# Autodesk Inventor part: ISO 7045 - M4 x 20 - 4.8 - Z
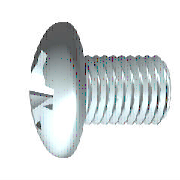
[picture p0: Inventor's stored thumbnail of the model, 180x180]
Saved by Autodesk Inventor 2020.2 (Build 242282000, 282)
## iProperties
Manager: www.cadconsulting.pl
Company: Fabian Stasiak CAD Consulting
Created: 2010-02
Part Number: ISO 7045 - M4 x 20 - 4.8 - Z
Material: Stal nierdzewna, 440C
Description: Śruba z łbem walcowym wypukłym z wgłębieniem krzyżowym
Document SubType Name: Modeling
Standard: ISO 7045
Designer: F.Stasiak
Standard Revision: 1994
Standards Organization: DIN
Language: pl-PL
Size Designation: M4 x 20 - 4.8 - Z
Categories: <MemberInstance><Categories><Category DisplayName="Mocowania" InternalName="e4da775c-781d-43d5-af7c-5136215cf5a6" Mnemonic="FSTN"><Category DisplayName="Śruby"
Density: 7.75 g/cm^3
Appearance: Metal-Stal
IsCustomPart: 0
Author: F.Stasiak
Subject: Zbiór ćwiczeń. Autodesk Inventor 2020. Kurs podstawowy
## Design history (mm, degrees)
body "Solid1"
sketch "Sketch1"
  geometry: L1 (20, 0)-(20, 2); L2 (20, 2)-(1.4, 2); L3 (3.962, 5.08)-(3.962, 5.08); L4 (-3.1, 0)-(-3.1, 3.892); L5 (-2.787, 1.994)-(-1.471, 1.338); L6 (-1.471, 1.338)-(-0.76, 0); L7 (-0.76, 0)-(20, 0); L8 (-8.108, 0)-(24.685, 0) reference; L9 (0, -1.016)-(0, 6.096) reference; L10 (-2.787, 1.994)-(-3.1, 2.15); L11 (-1.771, 3.938)-(-3.1, 3.892); L12 (-1.771, 3.938)-(0, 4); L13 (0, 4)-(0, 1.811); L14 (0, 1.811)-(0.971, 1.811); L15 (0.971, 1.811)-(1.4, 2); L16 (1.4, 2)-(0, 2); A1 r 6.5 centre (3.4, 0) between (-1.771, 3.938) and (-3.1, 0)
  constraints: 28 end point, 5 point on line, 4 collinear, 4 point on circle, 3 parallel, 2 perpendicular, 1 centre point, 1 horizontal, 1 tangent
  dimensions: "d1" = 4 diameter of L2 L7 (= GD); "d2" = 2.34 distance from line of L6.end L4 (= STI); "d16" = 4.3 diameter of L10.end L7 (= SDM); "d17" = 62 deg angle of L6 L7; "d19" = 26.5 deg angle of L5 L7; "d23" = 8 diameter of L12.end L7 (= KOD); "d24" = 2 deg angle of L12 L7 (= KEWI); "d25" = 3.1 distance between parallel lines of L4 L13 (= KOH); "d26" = 6.5 radius of A1 (= KR); "d28" = 3.62111 diameter of L14 L7 (= BDM); "d29" = 18.6 distance of L1.end L2.end (= GEL); "d30" = 0.42941 horizontal distance of L14.end L2.end (= GAL); "d31" = 20 distance between parallel lines of L13 L1 (= NLG)
revolve "Body" stored, may be unused: angle "d18" = 90 deg
node "IDS_WORKPLANE{1}"
sketch "Sketch2"
  geometry: L1 (-6.07, 0)-(8.852, 0) reference; L2 (0, -6.07)-(0, 8.852) reference; L3 (0, 2.15)-(0, 0); L4 (0, 0)-(2.15, 0); L5 (0, 0)-(6.721, 6.721); L6 (0.415, 2.11)-(0.286, 1.036); L7 (2.11, 0.415)-(1.036, 0.286); L8 (2.11, -0.415)-(1.036, -0.286); L9 (0.415, -2.11)-(0.286, -1.036); L10 (-0.415, 2.11)-(-0.286, 1.036); L11 (-2.11, 0.415)-(-1.036, 0.286); L12 (-0.415, -2.11)-(-0.286, -1.036); L13 (-2.11, -0.415)-(-1.036, -0.286); C1 r 3.938 at (0, 0) reference; A1 r 0.86 centre (0, 0) between (0.86, 0) and (0, 0.86); A2 r 0.297 centre (0.581, 1.001) between (0.286, 1.036) and (0.791, 0.791); A3 r 0.297 centre (1.001, 0.581) between (0.791, 0.791) and (1.036, 0.286); A4 r 2.15 centre (0, 0) between (2.15, 0) and (2.11, 0.415); A5 r 2.15 centre (0, 0) between (0.415, 2.11) and (0, 2.15); A6 r 2.15 centre (0, 0) between (2.11, 0.415) and (0.415, 2.11); A7 r 2.15 centre (0, 0) between (0, -2.15) and (0.415, -2.11); A8 r 2.15 centre (0, 0) between (0.415, -2.11) and (2.11, -0.415); A9 r 2.15 centre (0, 0) between (2.11, -0.415) and (2.15, 0); A10 r 0.297 centre (0.581, -1.001) between (0.791, -0.791) and (0.286, -1.036); A11 r 0.297 centre (1.001, -0.581) between (1.036, -0.286) and (0.791, -0.791); A12 r 0.297 centre (-0.581, 1.001) between (-0.791, 0.791) and (-0.286, 1.036); A13 r 0.297 centre (-1.001, 0.581) between (-1.036, 0.286) and (-0.791, 0.791); A14 r 2.15 centre (0, 0) between (-2.11, 0.415) and (-2.15, 0); A15 r 2.15 centre (0, 0) between (-0.415, 2.11) and (-2.11, 0.415); A16 r 2.15 centre (0, 0) between (0, 2.15) and (-0.415, 2.11); A17 r 2.15 centre (0, 0) between (-2.15, 0) and (-2.11, -0.415); A18 r 2.15 centre (0, 0) between (-2.11, -0.415) and (-0.415, -2.11); A19 r 2.15 centre (0, 0) between (-0.415, -2.11) and (0, -2.15); A20 r 0.297 centre (-1.001, -0.581) between (-0.791, -0.791) and (-1.036, -0.286); A21 r 0.297 centre (-0.581, -1.001) between (-0.286, -1.036) and (-0.791, -0.791); A22 r 1.075 centre (0, 0) between (1.075, 0) and (0, 1.075)
  constraints: 46 point on circle, 25 symmetric about line, 22 centre point, 22 end point, 6 tangent, 4 coincident, 3 collinear, 3 point on line, 1 midpoint, 1 perpendicular, 22 other
  dimensions: "d4" = 45 deg angle of L5 L4; "d5" = 1.72 diameter of A1 (= 0.4 x SDM); "d6" = 4.3 diameter of A6 (= SDM); "d7" = 0.415 distance from line of L6.start L3 (= 0.5 x SBR); "d20" = 2.15 diameter of A22 (= 0.5 x SDM)
extrude "Slot" join sketch "Sketch2" taper "d21" = 5 deg; stored distance "d54" = 10
revolve "Cut" stored, may be unused: angle "d56" = 90 deg
sketch "Sketch4"
  geometry: L1 (-9, 0)-(9, 0) reference; L2 (0, -9)-(0, 9) reference; L3 (0, 0)-(6.428, 6.428); L4 (0, 0)-(6.428, -6.428); L5 (0, 0)-(-6.428, 6.428); L6 (0, 0)-(-6.428, -6.428); L7 (1.52, 1.52)-(0, 0.208); L8 (-1.52, 1.52)-(-0.208, 0); L9 (-1.52, -1.52)-(0, -0.208); L10 (1.52, -1.52)-(0.207, 0); L11 (1.52, 1.52)-(0.208, 0); L12 (-1.52, 1.52)-(0, 0.208); L13 (-1.52, -1.52)-(-0.207, 0); L14 (1.52, -1.52)-(0, -0.208); C1 r 3.938 at (0, 0) reference; A1 r 0.208 centre (0, 0) between (0, 0.208) and (-0.208, 0); A2 r 2.15 centre (0, 0) between (1.52, 1.52) and (1.52, -1.52); 1 further point
  constraints: 24 end point, 10 point on line, 7 point on circle, 3 perpendicular, 3 symmetric about line, 2 centre point, 2 coincident, 3 other
  dimensions: "d11" = 0.415 diameter of A1 (= 0.5 x SBR); "d14" = 45 deg angle of L3 L1; "d35" = 1.52028 distance from line of L1 L7.start (= 0.353553 x SDM)
extrude "Star Cut" cut sketch "Sketch4" distance "d12" = 3.1 (= KOH); taper "d13" = -10 deg
fillet "Fillet1" dims "d32" = 1.3 (= RR)
fillet "Fillet2" dims "d22" = 0.166 (= 0.2 x SBR)
feature "Thread" dims "d8" = 18.6 (= GEL), "d9" = 0
chamfer "Chamfer1" distance "d36" = 0.42941 (= -0.5 x SPD + 0.5 x GD); stored, may be unused: second distance "d37" = 0.42952 (computed from GUL), angle "d81" = 45 deg
fillet "Fillet3" dims "d84" = 0.2 (= R)
workplane "Work Plane3"
other parameters: "GD" = 4 [user parameter; used in 2 equation terms], "NLG" = 20 [user parameter; used in 1 equation term], "GEL" = 18.6 [user parameter; used in 2 equation terms], "KOD" = 8 [user parameter; used in 1 equation term], "KOH" = 3.1 [user parameter; used in 3 equation terms], "SDM" = 4.3 [user parameter; used in 5 equation terms], "STI" = 2.34 [user parameter; used in 1 equation term], "SBR" = 0.83 [user parameter; used in 3 equation terms], "KEWI" = 2 deg [user parameter; used in 1 equation term], "d3" = -3.1 (= -KOH), "d10" = 0, "KR" = 6.5 [user parameter; used in 1 equation term], "BDM" = 3.62111 [user parameter; used in 1 equation term], "GAL" = 0.42941 (= 0.61345 x PTC) [user parameter; used in 1 equation term], "GUL" = 0.42941 (= 0.61345 x PTC) [user parameter; used in 1 equation term], "RR" = 1.3 [user parameter; used in 1 equation term], "SPD" = 3.14117 (= NND - 1.2269 x PTC) [user parameter; used in 1 equation term], "d82" = 0, "d83" = 0, "R" = 0.2 [user parameter; used in 1 equation term], "PTC" = 0.7 [user parameter; used in 5 equation terms], "THREADDIA" = 4 [user parameter; used in 1 equation term], "TOA" = 30 deg [user parameter], "TPU" = 14.28571 (computed from PTC) [user parameter], "NND" = 4 [user parameter; used in 1 equation term], "GD1" = 3.14117 (= THREADDIA - 1.2269 x PTC) [user parameter]
